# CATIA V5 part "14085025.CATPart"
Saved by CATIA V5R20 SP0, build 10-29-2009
Part number: 14085025
Definition: NONE
Nomenclature: 14085025
Source: Unknown
Description: 14085025
Bounding box of the stored display mesh (mm): x -12.5 to 50, y -56.5 to 46.401, z -46.6 to 46.6
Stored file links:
  C:\Users\Utente\Desktop\IO LAVORO\3D X SITO CF\X SITO\PLASTICA\RF2\14085025.CATPart
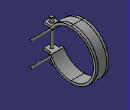
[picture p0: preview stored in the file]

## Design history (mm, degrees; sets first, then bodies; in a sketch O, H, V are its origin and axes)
Body1 "14085025" (main body)
  Solid1: solid without history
